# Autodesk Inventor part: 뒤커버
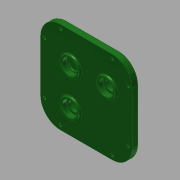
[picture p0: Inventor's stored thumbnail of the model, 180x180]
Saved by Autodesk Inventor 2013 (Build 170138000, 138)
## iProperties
Created: 2016-12
Part Number: 뒤커버
Material: 일반
Document SubType Name: Modeling
Designer: mduedu
Density: 1 g/cm^3
Author: mduedu
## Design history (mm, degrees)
sketch "스케치1"
  geometry: L1 (-46, 42)-(-46, -36); L2 (-16, 72)-(62, 72); L3 (92, 42)-(92, -36); L4 (62, -66)-(-16, -66); A1 r 30 centre (-16, -36) between (-46, -36) and (-16, -66); A2 r 30 centre (62, 42) between (92, 42) and (62, 72); A3 r 30 centre (62, -36) between (62, -66) and (92, -36); A4 r 30 centre (-16, 42) between (-16, 72) and (-46, 42); 1 further point
  constraints: 8 end point, 8 point on circle, 8 tangent, 4 centre point, 3 equal radius, 2 perpendicular, 1 horizontal, 1 vertical
  dimensions: "d80" = 30 radius of A2; "d81" = 138 distance between parallel lines of L4 L2; "d82" = 92 distance from line of L3 point (0, 0); "d114" = 46 distance from line of L1 point (0, 0); "d115" = 72 distance from line of L2 point (0, 0)
extrude "돌출1" new body sketch "스케치1" distance "d3" = 10; taper "d4" = 0 deg
sketch "스케치2"
  geometry: C1 r 14 at (0, 26); 1 further point
  constraints: 1 centre point, 1 vertical alignment
  dimensions: "d5" = 28 diameter of C1; "d6" = 26 distance of C1.centre point (0, 0)
extrude "돌출2" join sketch "스케치2" distance "d7" = 3; taper "d8" = 0 deg
sketch "스케치3"
  geometry: C1 r 14 at (0, -28.87); C2 r 14 at (0, 26) reference; C3 r 14 at (54.87, 26); 1 further point
  constraints: 2 centre point, 1 horizontal alignment, 1 vertical alignment
  dimensions: "d9" = 28 diameter of C1; "d69" = 54.87 distance of C1.centre C2.centre; "d83" = 28 diameter of C3; "d84" = 54.87 distance of C3.centre C2.centre
extrude "돌출3" join sketch "스케치3" distance "d11" = 3; taper "d12" = 0 deg
hole "구멍1" diameter "d15" = 22; stored, may be unused: countersink angle "d19" = 90 deg, drill point angle "d21" = 0 deg; dims "d13" = 10, "d14" = 10, "d16" = 6, "d17" = 4, "d18" = 2, "d20" = 7
hole "구멍2" diameter "d24" = 18; stored, may be unused: countersink angle "d28" = 90 deg, drill point angle "d30" = 0 deg; dims "d22" = 10, "d23" = 10, "d25" = 6, "d26" = 4, "d27" = 2, "d29" = 1
hole "구멍3" diameter "d33" = 22; stored, may be unused: countersink angle "d37" = 90 deg, drill point angle "d39" = 0 deg; dims "d31" = 10, "d32" = 10, "d34" = 6, "d35" = 4, "d36" = 2, "d38" = 7
hole "구멍7" diameter "d87" = 22; stored, may be unused: countersink angle "d91" = 90 deg, drill point angle "d93" = 0 deg; dims "d85" = 10, "d86" = 10, "d88" = 6, "d89" = 4, "d90" = 2, "d92" = 7
sketch "스케치4"
  geometry: C1 r 14 at (0, -28.87) reference; C2 r 18 at (0, -28.87); C3 r 14 at (-54.87, 26) reference; C4 r 18 at (-54.87, 26); 1 further point
  constraints: 2 centre point, 2 coincident
  dimensions: "d40" = 36 diameter of C2; "d94" = 36 diameter of C4
extrude "돌출4" join sketch "스케치4" distance "d41" = 4; taper "d42" = 0 deg
hole "구멍4" diameter "d45" = 22; stored, may be unused: countersink angle "d49" = 90 deg, drill point angle "d51" = 0 deg; dims "d43" = 10, "d44" = 10, "d46" = 6, "d47" = 4, "d48" = 2, "d50" = 7
hole "구멍8" diameter "d97" = 22; stored, may be unused: countersink angle "d101" = 90 deg, drill point angle "d103" = 0 deg; dims "d95" = 10, "d96" = 10, "d98" = 6, "d99" = 4, "d100" = 2, "d102" = 7
hole "구멍5" diameter "d54" = 15; stored, may be unused: countersink angle "d58" = 90 deg, drill point angle "d60" = 0 deg; dims "d52" = 10, "d53" = 10, "d55" = 6, "d56" = 4, "d57" = 2, "d59" = 7
hole "구멍9" diameter "d106" = 15; stored, may be unused: countersink angle "d110" = 90 deg, drill point angle "d112" = 0 deg; dims "d104" = 10, "d105" = 10, "d107" = 6, "d108" = 4, "d109" = 2, "d111" = 7
fillet "모깎기1" dims "d61" = 0.3
fillet "모깎기2" dims "d62" = 2
chamfer "모따기1" distance "d63" = 1; stored, may be unused: second distance "d64" = 2, angle "d65" = 45 deg
fillet "모깎기3" dims "d66" = 2
fillet "모깎기4" dims "d67" = 2
fillet "모깎기5" dims "d68" = 2
sketch "스케치5"
  geometry: L1 (-62, 72)-(16, 72) reference; L2 (-92, -36)-(-92, 42) reference; L3 (16, -66)-(-62, -66) reference; L4 (46, 42)-(46, -36) reference; L5 (16, 66)-(-62, 66); L6 (-86, 42)-(-86, -36); L7 (-62, -60)-(16, -60); L8 (40, -36)-(40, 42); A1 r 30 centre (-62, 42) between (-62, 72) and (-92, 42) reference; A2 r 30 centre (-62, -36) between (-92, -36) and (-62, -66) reference; A3 r 30 centre (16, -36) between (16, -66) and (46, -36) reference; A4 r 30 centre (16, 42) between (46, 42) and (16, 72) reference; A5 r 24 centre (-62, 42) between (-62, 66) and (-86, 42); A6 r 24 centre (-62, -36) between (-86, -36) and (-62, -60); A7 r 24 centre (16, -36) between (16, -60) and (40, -36); A8 r 24 centre (16, 42) between (40, 42) and (16, 66)
  constraints: 8 end point, 8 point on circle, 4 centre point, 7 other
  dimensions: "d113" = 6 distance between parallel lines of L6 L2
sketch "스케치6"
  geometry: L1 (16, 66)-(-62, 66) reference; L2 (40, -36)-(40, 42) reference; L3 (-62, -60)-(16, -60) reference; L4 (-86, 42)-(-86, -36) reference; A1 r 24 centre (16, 42) between (40, 42) and (16, 66) reference; A2 r 24 centre (16, -36) between (16, -60) and (40, -36) reference; A3 r 24 centre (-62, -36) between (-86, -36) and (-62, -60) reference; A4 r 24 centre (-62, 42) between (-62, 66) and (-86, 42) reference; 8 further points
  constraints: 8 coincident
hole "구멍6" sketch "스케치6" at (-62, 66), (-86, 42), (-86, -36), (-62, -60), (16, -60), (40, -36), (40, 42), (16, 66) diameter "d71" = 4.5; stored, may be unused: countersink angle "d75" = 90 deg, drill point angle "d77" = 0 deg; dims "d72" = 6, "d73" = 8, "d74" = 4.6, "d76" = 8
node "솔리드1"
